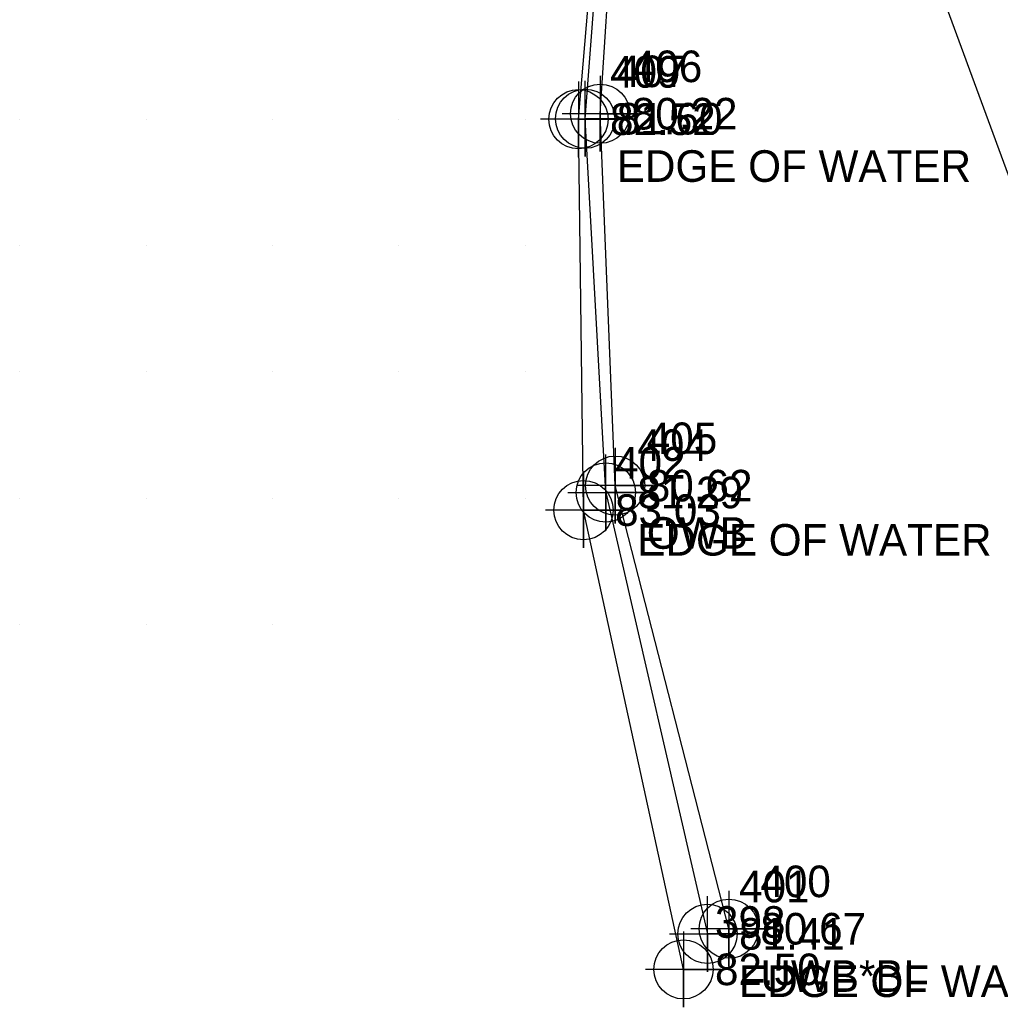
# Model space of a CAD drawing. Extents: x 1988140 to 1988766, y 249950 to 250250.
# Drawn here: x 1988380 to 1988457.6, y 249949.7 to 250027.9 of the extents above; entities that cross this region are included whole.
import ezdxf

# ---------------------------------------------------------------- set-up
doc = ezdxf.new("R2010")
doc.units = 0
for name, color, linetype in [('Exist DTM Breakline', 7, 'Continuous'), ('Exist DTM Breakline Cogo Comment', 7, 'Continuous'), ('Exist DTM Breakline Cogo Elevation', 7, 'Continuous'), ('Exist DTM Breakline Cogo Number', 7, 'Continuous'), ('Exist DTM Breakline Cogo Point CELL', 7, 'Continuous'), ('Exist DTM Breakline Underwater', 7, 'Continuous'), ('Exist DTM QL2 LIDAR Elevation Point', 7, 'Continuous'), ('Exist Hydro Stream or Body of Water', 7, 'Continuous'), ('Exist Hydro Stream or Body of Water Cogo Comment', 7, 'Continuous'), ('Exist Hydro Stream or Body of Water Cogo Elevation', 7, 'Continuous'), ('Exist Hydro Stream or Body of Water Cogo Number', 7, 'Continuous'), ('Exist Hydro Stream or Body of Water Cogo Point CELL', 7, 'Continuous')]:
    doc.layers.add(name, color=color, linetype=linetype)

msp = doc.modelspace()

# ---------------------------------------------------------------- linework, layer by layer
at = {"layer": 'Exist DTM Breakline'}
msp.add_lwpolyline([(1988432.5356, 249952.6918), (1988424.6294, 249989.0571), (1988424.2247, 250020.0082), (1988425.5053, 250034.9767), (1988423.2372, 250041.8418), (1988412.8446, 250078.35)], dxfattribs=at)
at = {"layer": 'Exist DTM Breakline Cogo Point CELL'}
for points in [[(1988425.95, 250023.4466), (1988425.95, 250017.4466), (1988425.95, 250020.4466), (1988428.95, 250020.4466), (1988422.95, 250020.4466)], [(1988424.2247, 250023.0082), (1988424.2247, 250017.0082), (1988424.2247, 250020.0082), (1988427.2247, 250020.0082), (1988421.2247, 250020.0082)], [(1988427.138, 249993.9941), (1988427.138, 249987.9941), (1988427.138, 249990.9941), (1988430.138, 249990.9941), (1988424.138, 249990.9941)], [(1988424.6294, 249992.0571), (1988424.6294, 249986.0571), (1988424.6294, 249989.0571), (1988427.6294, 249989.0571), (1988421.6294, 249989.0571)], [(1988436.1327, 249958.9094), (1988436.1327, 249952.9094), (1988436.1327, 249955.9094), (1988439.1327, 249955.9094), (1988433.1327, 249955.9094)], [(1988432.5356, 249955.6918), (1988432.5356, 249949.6918), (1988432.5356, 249952.6918), (1988435.5356, 249952.6918), (1988429.5356, 249952.6918)]]:
    msp.add_lwpolyline(points, dxfattribs=at)
for centre in [(1988425.95, 250020.4466), (1988424.2247, 250020.0082), (1988427.138, 249990.9941), (1988424.6294, 249989.0571), (1988436.1327, 249955.9094), (1988432.5356, 249952.6918)]:
    msp.add_circle(centre, 2.344, dxfattribs=at)
at = {"layer": 'Exist DTM Breakline Underwater'}
for points in [[(1988432.5434, 250186.7094), (1988425.7037, 250133.7144), (1988438.98, 250078.1677), (1988446.627, 250047.162), (1988463.2661, 250001.9742), (1988462.1612, 249955.3502)], [(1988436.1327, 249955.9094), (1988427.138, 249990.9941), (1988425.95, 250020.4466), (1988426.9175, 250035.4976), (1988425.2614, 250042.5346), (1988415.9105, 250079.3465), (1988417.7936, 250087.3716)]]:
    msp.add_lwpolyline(points, dxfattribs=at)
at = {"layer": 'Exist DTM QL2 LIDAR Elevation Point'}
for p, q in [((1988380, 250020), (1988380, 250020)), ((1988390, 250020), (1988390, 250020)), ((1988400, 250020), (1988400, 250020)), ((1988410, 250020), (1988410, 250020)), ((1988420, 250020), (1988420, 250020)), ((1988380, 250010), (1988380, 250010)), ((1988390, 250010), (1988390, 250010)), ((1988400, 250010), (1988400, 250010)), ((1988410, 250010), (1988410, 250010)), ((1988420, 250010), (1988420, 250010)), ((1988380, 250000), (1988380, 250000)), ((1988390, 250000), (1988390, 250000)), ((1988400, 250000), (1988400, 250000)), ((1988410, 250000), (1988410, 250000)), ((1988420, 250000), (1988420, 250000)), ((1988380, 249990), (1988380, 249990)), ((1988390, 249990), (1988390, 249990)), ((1988400, 249990), (1988400, 249990)), ((1988410, 249990), (1988410, 249990)), ((1988420, 249990), (1988420, 249990)), ((1988380, 249980), (1988380, 249980)), ((1988390, 249980), (1988390, 249980)), ((1988400, 249980), (1988400, 249980))]:
    msp.add_line(p, q, dxfattribs=at)
at = {"layer": 'Exist Hydro Stream or Body of Water'}
msp.add_line((1988426.3876, 249990.4525), (1988434.4391, 249955.5004), dxfattribs=at)
msp.add_lwpolyline([(1988426.3876, 249990.4525), (1988424.7619, 250020.0506), (1988425.9258, 250035.2006), (1988423.8559, 250042.0862), (1988414.1552, 250078.1093), (1988416.1489, 250087.1232), (1988406.0862, 250116.7149), (1988400.9098, 250127.7446), (1988403.8774, 250149.9815), (1988410.3915, 250190.2759)], dxfattribs=at)
at = {"layer": 'Exist Hydro Stream or Body of Water Cogo Point CELL'}
for points in [[(1988421.7619, 250020.0506), (1988427.7619, 250020.0506), (1988424.7619, 250020.0506), (1988424.7619, 250017.0506), (1988424.7619, 250023.0506)], [(1988423.3876, 249990.4525), (1988429.3876, 249990.4525), (1988426.3876, 249990.4525), (1988426.3876, 249987.4525), (1988426.3876, 249993.4525)], [(1988431.4391, 249955.5004), (1988437.4391, 249955.5004), (1988434.4391, 249955.5004), (1988434.4391, 249952.5004), (1988434.4391, 249958.5004)]]:
    msp.add_lwpolyline(points, dxfattribs=at)
for centre in [(1988424.7619, 250020.0506), (1988426.3876, 249990.4525), (1988434.4391, 249955.5004)]:
    msp.add_circle(centre, 2.344, dxfattribs=at)

# ---------------------------------------------------------------- texts
at = {"layer": 'Exist DTM Breakline Cogo Comment'}
for s, p in [('OWB', (1988429.638, 249985.9941)), ('UWB*BL', (1988438.6327, 249950.9094))]:
    msp.add_text(s, height=2.5, dxfattribs=at).set_placement(p)
at = {"layer": 'Exist DTM Breakline Cogo Elevation'}
for s, p in [('80.22', (1988428.45, 250019.1966)), ('82.52', (1988426.7247, 250018.7582)), ('80.62', (1988429.638, 249989.7441)), ('83.03', (1988427.1294, 249987.8071)), ('80.67', (1988438.6327, 249954.6594)), ('82.50', (1988435.0356, 249951.4418))]:
    msp.add_text(s, height=2.5, dxfattribs=at).set_placement(p)
at = {"layer": 'Exist DTM Breakline Cogo Number'}
for s, p in [('409', (1988426.7247, 250022.5082)), ('406', (1988428.45, 250022.9466)), ('405', (1988429.638, 249993.4941)), ('402', (1988427.1294, 249991.5571)), ('400', (1988438.6327, 249958.4094)), ('398', (1988435.0356, 249955.1918))]:
    msp.add_text(s, height=2.5, dxfattribs=at).set_placement(p)
at = {"layer": 'Exist Hydro Stream or Body of Water Cogo Comment'}
for p in [(1988427.2619, 250015.0506), (1988428.8876, 249985.4525), (1988436.9391, 249950.5004)]:
    msp.add_text('EDGE OF WATER', height=2.5, dxfattribs=at).set_placement(p)
at = {"layer": 'Exist Hydro Stream or Body of Water Cogo Elevation'}
for s, p in [('81.60', (1988427.2619, 250018.8006)), ('81.29', (1988428.8876, 249989.2025)), ('81.41', (1988436.9391, 249954.2504))]:
    msp.add_text(s, height=2.5, dxfattribs=at).set_placement(p)
at = {"layer": 'Exist Hydro Stream or Body of Water Cogo Number'}
for s, p in [('407', (1988427.2619, 250022.5506)), ('404', (1988428.8876, 249992.9525)), ('401', (1988436.9391, 249958.0004))]:
    msp.add_text(s, height=2.5, dxfattribs=at).set_placement(p)

doc.saveas('drawing.dxf')
